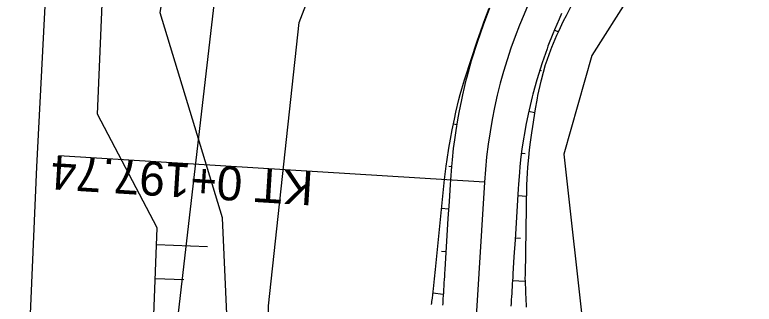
# Model space of a CAD drawing. Extents: x -583470 to -583050, y -1165714 to -1165417.
# Drawn here: x -583387.17 to -583343.82, y -1165610.45 to -1165593.45 of the extents above; entities that cross this region are included whole.
import ezdxf

# ---------------------------------------------------------------- set-up
doc = ezdxf.new("R2010")
doc.units = 0
for name, color, linetype in [('42', 7, 'Continuous'), ('60', 7, 'Continuous'), ('62', 7, 'Continuous'), ('Hranice parcel', 7, 'Continuous'), ('Parcelní čísla', 7, 'Continuous'), ('Rám', 7, 'Continuous'), ('Sítě', 7, 'Continuous'), ('Šrafy', 7, 'Continuous')]:
    doc.layers.add(name, color=color, linetype=linetype)

msp = doc.modelspace()

# ---------------------------------------------------------------- linework, layer by layer
at = {"layer": '42'}
for points in [[(-583384.86, -1165633.85), (-583379.55, -1165624.92), (-583378.83, -1165605.97), (-583382.33, -1165599.28), (-583381.32, -1165575.74)], [(-583384.99, -1165636.09), (-583373.54, -1165638.1), (-583375.11, -1165632.24), (-583372.59, -1165629.75), (-583374.48, -1165616.67), (-583375, -1165605.38), (-583378.65, -1165593.33), (-583377.9, -1165588.81)]]:
    msp.add_lwpolyline(points, dxfattribs=at)
at = {"layer": '60'}
for points in [[(-583378.87, -1165606.93), (-583375.87, -1165607.05)], [(-583378.94, -1165608.93), (-583377.26, -1165609)]]:
    msp.add_lwpolyline(points, dxfattribs=at)
at = {"layer": '62'}
msp.add_lwpolyline([(-583379.741, -1165694.56), (-583379.57, -1165690.87), (-583377.81, -1165675.52), (-583374, -1165654.25), (-583372.12, -1165641.43), (-583371.79, -1165638.08), (-583372.3, -1165610.54), (-583370.49, -1165593.91), (-583364.41, -1165578.01), (-583353.13, -1165562.49), (-583348.06, -1165556.64), (-583342.86, -1165548.6), (-583339.71, -1165538.95), (-583338.99, -1165532.81), (-583338.38, -1165526.75), (-583340.63, -1165516.91), (-583347.05, -1165504.24), (-583349.624, -1165498.549)], dxfattribs=at)
at = {"layer": 'Hranice parcel'}
msp.add_lwpolyline([(-583359.64, -1165603.276), (-583384.591, -1165601.725)], dxfattribs=at)
at = {"layer": 'Parcelní čísla'}
msp.add_line((-583359.64, -1165603.276), (-583360.991, -1165625.018), dxfattribs=at)
msp.add_arc((-583329.697, -1165605.137), 30, 89.2824, 176.4435, dxfattribs=at)
at = {"layer": 'Rám'}
for points in [[(-583202.69, -1165538.68), (-583225.12, -1165531.51), (-583247.31, -1165545.19), (-583283.21, -1165574.06), (-583292.71, -1165580.22), (-583304.73, -1165581.14), (-583316.86, -1165578.96), (-583335.26, -1165581.29), (-583341.42, -1165583.09), (-583347.21, -1165586.62), (-583351.13, -1165592.35), (-583353.34, -1165595.85), (-583354.98, -1165601.64), (-583352.56, -1165623.43)], [(-583372.44, -1165649.28), (-583380.56, -1165643.71), (-583384.65, -1165640.82), (-583384.34, -1165635.13), (-583380.11, -1165632.63), (-583380.02, -1165632.08), (-583374.92, -1165587.93), (-583361.04, -1165570.69)]]:
    msp.add_lwpolyline(points, dxfattribs=at)
at = {"layer": 'Sítě'}
for points in [[(-583362.734, -1165610.469), (-583362.721, -1165610.361), (-583362.713, -1165610.281), (-583362.692, -1165610.092), (-583362.671, -1165609.904), (-583362.651, -1165609.716), (-583362.631, -1165609.528), (-583362.613, -1165609.366), (-583362.61, -1165609.34), (-583362.591, -1165609.151), (-583362.571, -1165608.963), (-583362.552, -1165608.775), (-583362.532, -1165608.587), (-583362.513, -1165608.399), (-583361.982, -1165603.13), (-583361.884, -1165602.341), (-583361.828, -1165601.94), (-583361.724, -1165601.276), (-583361.634, -1165600.757), (-583361.532, -1165600.217), (-583361.402, -1165599.584), (-583361.309, -1165599.167), (-583361.131, -1165598.421), (-583361.055, -1165598.125), (-583360.803, -1165597.274), (-583360.747, -1165597.099), (-583360.434, -1165596.142), (-583360.416, -1165596.082), (-583360.093, -1165595.065), (-583360.074, -1165595.009), (-583359.739, -1165594.058), (-583359.677, -1165593.89), (-583359.355, -1165593.062)], [(-583359.335, -1165593.07), (-583359.658, -1165593.897), (-583359.721, -1165594.064), (-583360.055, -1165595.016), (-583360.073, -1165595.071), (-583360.392, -1165596.089), (-583360.409, -1165596.149), (-583360.676, -1165597.117), (-583360.722, -1165597.294), (-583360.926, -1165598.154), (-583360.991, -1165598.451), (-583361.142, -1165599.199), (-583361.218, -1165599.616), (-583361.322, -1165600.25), (-583361.401, -1165600.789), (-583361.467, -1165601.307), (-583361.54, -1165601.968), (-583361.577, -1165602.367), (-583361.636, -1165603.152), (-583361.652, -1165603.414), (-583361.714, -1165604.412), (-583361.776, -1165605.41), (-583361.838, -1165606.408), (-583361.9, -1165607.406), (-583361.962, -1165608.404), (-583361.964, -1165608.433), (-583361.976, -1165608.621), (-583361.987, -1165608.81), (-583361.999, -1165608.999), (-583362.011, -1165609.187), (-583362.023, -1165609.376), (-583362.024, -1165609.402), (-583362.034, -1165609.565), (-583362.046, -1165609.754), (-583362.058, -1165609.942), (-583362.07, -1165610.131), (-583362.081, -1165610.32), (-583362.086, -1165610.4), (-583362.093, -1165610.508)], [(-583354.594, -1165593.008), (-583354.854, -1165593.505), (-583355.016, -1165593.83), (-583355.301, -1165594.432), (-583355.408, -1165594.669), (-583355.709, -1165595.378), (-583355.767, -1165595.522), (-583356.069, -1165596.345), (-583356.083, -1165596.393), (-583356.319, -1165597.29), (-583356.332, -1165597.342), (-583356.521, -1165598.193), (-583356.552, -1165598.348), (-583356.69, -1165599.101), (-583356.732, -1165599.361), (-583356.826, -1165600.014), (-583356.881, -1165600.376), (-583356.96, -1165600.924), (-583357.017, -1165601.39), (-583357.064, -1165601.837), (-583357.113, -1165602.409), (-583357.136, -1165602.753), (-583357.167, -1165603.429), (-583357.258, -1165608.725), (-583357.261, -1165608.914), (-583357.256, -1165609.104), (-583357.249, -1165609.294), (-583357.241, -1165609.484), (-583357.234, -1165609.674), (-583357.233, -1165609.7), (-583357.226, -1165609.864), (-583357.218, -1165610.054), (-583357.209, -1165610.244), (-583357.201, -1165610.434), (-583357.192, -1165610.624)], [(-583355.112, -1165593.385), (-583355.264, -1165593.72), (-583355.53, -1165594.336), (-583355.63, -1165594.578), (-583355.913, -1165595.302), (-583355.968, -1165595.448), (-583356.26, -1165596.281), (-583356.276, -1165596.329), (-583356.555, -1165597.22), (-583356.57, -1165597.272), (-583356.804, -1165598.12), (-583356.844, -1165598.275), (-583357.023, -1165599.027), (-583357.079, -1165599.286), (-583357.211, -1165599.941), (-583357.278, -1165600.306), (-583357.369, -1165600.861), (-583357.438, -1165601.333), (-583357.496, -1165601.785), (-583357.56, -1165602.364), (-583357.592, -1165602.714), (-583357.643, -1165603.4), (-583357.66, -1165603.662), (-583357.722, -1165604.66), (-583357.784, -1165605.658), (-583357.846, -1165606.656), (-583357.908, -1165607.654), (-583357.97, -1165608.652), (-583357.972, -1165608.681), (-583357.983, -1165608.87), (-583357.995, -1165609.058), (-583358.007, -1165609.247), (-583358.019, -1165609.436), (-583358.03, -1165609.624), (-583358.032, -1165609.65), (-583358.042, -1165609.813), (-583358.054, -1165610.002), (-583358.066, -1165610.19), (-583358.077, -1165610.379), (-583358.089, -1165610.568)]]:
    msp.add_lwpolyline(points, dxfattribs=at)
at = {"layer": 'Šrafy'}
for p, q in [((-583355.314, -1165594.46), (-583355.542, -1165594.365)), ((-583360.091, -1165595.058), (-583360.071, -1165595.065)), ((-583356.29, -1165596.747), (-583356.396, -1165596.713)), ((-583360.807, -1165597.452), (-583360.762, -1165597.465)), ((-583356.706, -1165599.201), (-583357.045, -1165599.127)), ((-583361.459, -1165599.863), (-583361.265, -1165599.904)), ((-583357.257, -1165601.617), (-583357.471, -1165601.589)), ((-583361.73, -1165602.348), (-583361.577, -1165602.369)), ((-583357.179, -1165604.117), (-583357.686, -1165604.079)), ((-583362.151, -1165604.812), (-583361.742, -1165604.854)), ((-583357.531, -1165606.594), (-583357.841, -1165606.575)), ((-583362.149, -1165607.325), (-583361.897, -1165607.351)), ((-583357.256, -1165609.116), (-583357.996, -1165609.07)), ((-583362.658, -1165609.786), (-583362.052, -1165609.848))]:
    msp.add_line(p, q, dxfattribs=at)
msp.add_lwpolyline([(-583389.634, -1165693.877), (-583387.68, -1165645.68), (-583386.91, -1165626.47), (-583385.88, -1165602.38), (-583384.78, -1165581.2), (-583382.27, -1165548.16), (-583380.06, -1165526.93), (-583377.27, -1165504.99), (-583376.322, -1165498.952)], dxfattribs=at)

# ---------------------------------------------------------------- texts
at = {"layer": 'Hranice parcel'}
msp.add_text('KT 0+197.74', height=2, rotation=176.4435, dxfattribs=at).set_placement((-583369.62, -1165602.655))

doc.saveas('drawing.dxf')
